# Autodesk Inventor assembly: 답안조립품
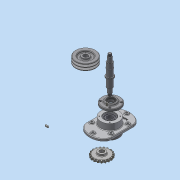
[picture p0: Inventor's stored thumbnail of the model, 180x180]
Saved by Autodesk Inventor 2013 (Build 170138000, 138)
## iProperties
Created: 2015-02
Part Number: 답안조립품
Document SubType Name: Assembly
Designer: Administrator
Author: Administrator
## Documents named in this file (12)
- C:\Users\Administrator\Desktop\450208V1020\답안조립품.iam
- C:\Users\Administrator\Desktop\450208V1020\본체.ipt
- C:\Users\Administrator\Desktop\450208V1020\3-축.ipt
- C:\Users\Administrator\Desktop\450208V1020\2-커버.ipt
- C:\Users\Administrator\Desktop\450208V1020\4-V벨트풀리.ipt
- C:\Users\Administrator\Desktop\450208V1020\6-베어링 6206.ipt
- C:\Users\Administrator\Desktop\450208V1020\7-부시.ipt
- C:\Users\Administrator\Desktop\450208V1020\8-오일실 30x42.ipt
- C:\Users\Administrator\Desktop\450208V1020\11-키 6x6.ipt
- C:\Users\Administrator\Desktop\450208V1020\9-M16-너트.ipt
- C:\Users\Administrator\Desktop\450208V1020\5-체인 스프로킷.ipt
- C:\Users\Administrator\Desktop\450208V1020\10-M6.ipt
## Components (13 placed, 10 different names)
1. 2-커버:1
2. 2-커버:2
3. 4-V벨트풀리:1
4. 6-베어링 6206:1
5. 6-베어링 6206:2
6. 7-부시:1
7. 8-8-오일실 30x42:1
8. 11-키 6x6:1
9. 9-M16 너트:1
10. 5-체인 스프로킷:1
11. 11-키 6x6:2
12. 10-M6:1
13. 3-축:1
